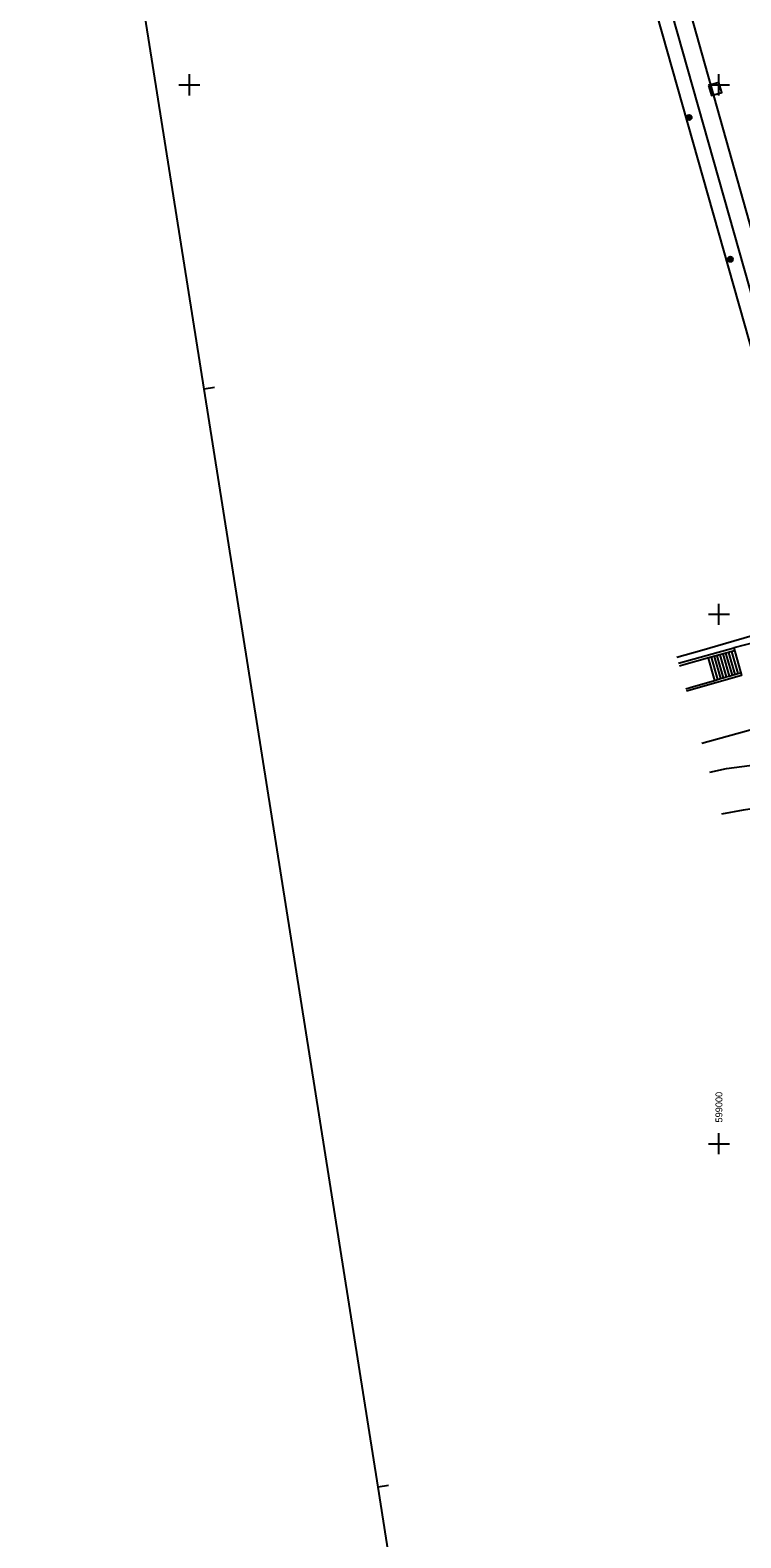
# Model space of a CAD drawing. Extents: x -599098 to -598820, y -1159597 to -1158744.
# Drawn here: x -599065 to -598997.9, y -1159187.2 to -1159044.8 of the extents above; entities that cross this region are included whole.
import ezdxf

# ---------------------------------------------------------------- set-up
doc = ezdxf.new("R2010")
doc.units = 0
for name, color, linetype in [('budovy', 7, 'Continuous'), ('hektometrická síť', 7, 'Continuous'), ('kresba', 7, 'Continuous'), ('mapový rám legenda', 7, 'Continuous'), ('značky IS', 7, 'Continuous'), ('zábradlí', 7, 'Continuous')]:
    doc.layers.add(name, color=color, linetype=linetype)

msp = doc.modelspace()

# ---------------------------------------------------------------- linework, layer by layer
at = {"layer": 'budovy'}
for p, q in [((-598989.86, -1159099.94), (-599011.12, -1159024.69)), ((-599009.81, -1159024.32), (-598989.59, -1159095.91))]:
    msp.add_line(p, q, dxfattribs=at)
for points in [[(-599003.98, -1159104.05), (-599001.63, -1159103.4), (-598994.6, -1159101.34), (-598994.47, -1159101.67), (-598992.12, -1159101.04), (-598992.22, -1159100.63), (-598989.86, -1159099.94)], [(-598987.58, -1159103.07), (-598995.97, -1159105.36), (-598996.65, -1159102.68), (-598998.61, -1159103.17), (-598997.86, -1159105.79), (-599003.06, -1159107.25)], [(-598999.72, -1159118.85), (-598997.67, -1159118.47), (-598996.48, -1159118.28), (-598993.7, -1159117.89), (-598990.87, -1159117.6), (-598988.16, -1159117.41), (-598986.21, -1159117.33), (-598983.03, -1159137.52), (-598984.55, -1159137.99), (-598982.84, -1159143.19), (-598980.75, -1159143.09), (-598978.24, -1159160.2), (-598972.13, -1159162.86)]]:
    msp.add_lwpolyline(points, dxfattribs=at)
at = {"layer": 'hektometrická síť'}
for p, q in [((-599051, -1159050), (-599049, -1159050)), ((-599050, -1159051), (-599050, -1159049)), ((-599001, -1159050), (-598999, -1159050)), ((-599000, -1159051), (-599000, -1159049)), ((-599001, -1159100), (-598999, -1159100)), ((-599000, -1159101), (-599000, -1159099)), ((-599001, -1159150), (-598999, -1159150)), ((-599000, -1159151), (-599000, -1159149))]:
    msp.add_line(p, q, dxfattribs=at)
at = {"layer": 'kresba'}
for p, q in [((-599001.02, -1159104.14), (-599000.41, -1159106.24)), ((-599000.74, -1159104.06), (-599000.14, -1159106.16)), ((-599000.47, -1159103.99), (-598999.86, -1159106.08)), ((-599000.19, -1159103.91), (-598999.59, -1159106)), ((-598999.92, -1159103.83), (-598999.31, -1159105.92)), ((-598999.64, -1159103.75), (-598999.04, -1159105.84)), ((-598999.37, -1159103.68), (-598998.76, -1159105.76)), ((-598999.09, -1159103.6), (-598998.49, -1159105.68)), ((-598998.81, -1159103.52), (-598998.21, -1159105.6)), ((-598999.28, -1159114.58), (-598993.05, -1159113.74)), ((-599000.85, -1159114.91), (-598999.28, -1159114.58))]:
    msp.add_line(p, q, dxfattribs=at)
for points in [[(-599001.01, -1159032.22), (-599001.51, -1159033.31), (-599004.93, -1159035.31), (-598989.66, -1159089.62), (-598983.28, -1159090.65), (-598979.01, -1159091.59)], [(-598978.93, -1159101.97), (-598978.36, -1159105.78), (-599001.63, -1159112.21)], [(-599003.81, -1159104.63), (-598998.61, -1159103.17)]]:
    msp.add_lwpolyline(points, dxfattribs=at)
at = {"layer": 'mapový rám legenda'}
for p, q in [((-599048.61, -1159078.74), (-599065.03, -1158975.03)), ((-599047.62, -1159078.58), (-599048.61, -1159078.74)), ((-599032.18, -1159182.45), (-599048.61, -1159078.74)), ((-599031.19, -1159182.29), (-599032.18, -1159182.45)), ((-599015.76, -1159286.16), (-599032.18, -1159182.45))]:
    msp.add_line(p, q, dxfattribs=at)
at = {"layer": 'značky IS'}
msp.add_lwpolyline([(-599000.98, -1159050.05), (-599000.7, -1159051.01), (-598999.74, -1159050.73), (-599000.02, -1159049.77)], close=True, dxfattribs=at)
for centre, radius in [((-599002.83, -1159053.08), 0.25), ((-599002.83, -1159053.08), 0.2), ((-599002.83, -1159053.08), 0.15), ((-599002.83, -1159053.08), 0.1), ((-599002.83, -1159053.08), 0.05), ((-598998.94, -1159066.47), 0.25), ((-598998.94, -1159066.47), 0.2), ((-598998.94, -1159066.47), 0.15), ((-598998.94, -1159066.47), 0.1), ((-598998.94, -1159066.47), 0.05)]:
    msp.add_circle(centre, radius, dxfattribs=at)
at = {"layer": 'zábradlí'}
for points in [[(-598998.53, -1159103.44), (-599001.09, -1159104.16), (-599003.32, -1159104.79), (-599003.73, -1159104.91)], [(-599003.12, -1159107.03), (-599002.72, -1159106.91), (-599000.41, -1159106.24), (-599000.14, -1159106.16), (-598999.86, -1159106.08), (-598999.59, -1159106), (-598999.31, -1159105.92), (-598999.04, -1159105.84), (-598998.76, -1159105.76), (-598998.49, -1159105.68), (-598998.21, -1159105.6), (-598997.94, -1159105.52)]]:
    msp.add_lwpolyline(points, dxfattribs=at)

# ---------------------------------------------------------------- texts
at = {"layer": 'hektometrická síť'}
msp.add_text('599000', height=0.65, rotation=90, dxfattribs=at).set_placement((-598999.68, -1159148))

doc.saveas('drawing.dxf')
